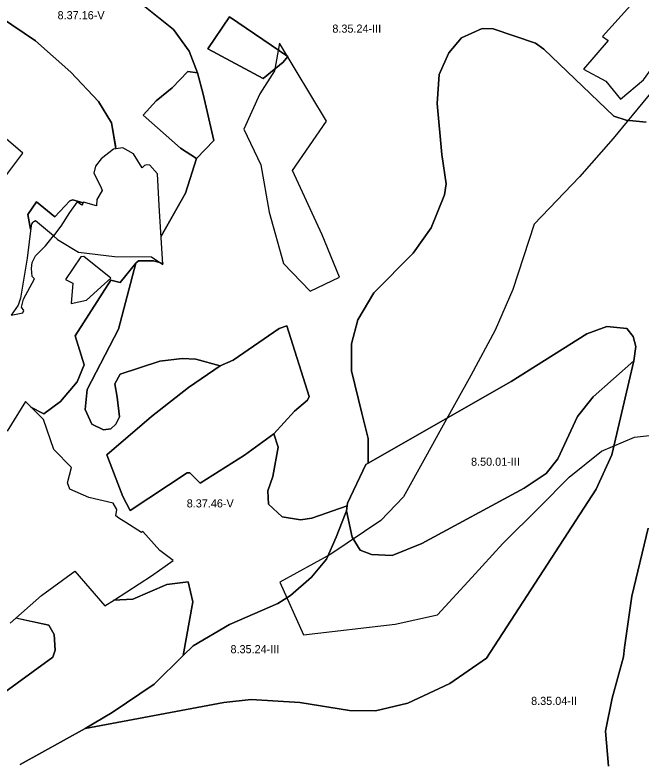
# Model space of a CAD drawing. Extents: x -547623 to -533936, y -1096714 to -1086523.
# Drawn here: x -542357 to -541585, y -1092131 to -1091207 of the extents above; entities that cross this region are included whole.
import ezdxf

# ---------------------------------------------------------------- set-up
doc = ezdxf.new("R2010")
doc.units = 0
for name, color, linetype in [('Vrstva 27', 7, 'Continuous'), ('Vrstva 28', 7, 'Continuous'), ('Vrstva 29', 7, 'Continuous')]:
    doc.layers.add(name, color=color, linetype=linetype)

msp = doc.modelspace()

# ---------------------------------------------------------------- linework, layer by layer
at = {"layer": 'Vrstva 28'}
for p, q in [((-542254, -1091151), (-542161.5, -1091225)), ((-542375, -1091210), (-542332, -1091239)), ((-542332, -1091239), (-542375, -1091210)), ((-542092.5, -1091209.5), (-542119.5, -1091249)), ((-542119.5, -1091249), (-542092.5, -1091209.5)), ((-542020.5, -1091258.5), (-542092.5, -1091209.5)), ((-542092.5, -1091209.5), (-542020.5, -1091258.5)), ((-542161.5, -1091225), (-542142.5, -1091252)), ((-541806.5, -1091235.5), (-541781, -1091224)), ((-541781, -1091224), (-541767.5, -1091224.5)), ((-541767.5, -1091224.5), (-541715, -1091242)), ((-542332, -1091239), (-542288.5, -1091278)), ((-542288.5, -1091278), (-542332, -1091239)), ((-541822, -1091254), (-541806.5, -1091235.5)), ((-541715, -1091242), (-541705, -1091249.5)), ((-542142.5, -1091252), (-542132, -1091278.5)), ((-542119.5, -1091249), (-542051, -1091285.5)), ((-542051, -1091285.5), (-542119.5, -1091249)), ((-541705, -1091249.5), (-541618.5, -1091332)), ((-542026.5, -1091265.5), (-542020.5, -1091258.5)), ((-542020.5, -1091258.5), (-542026.5, -1091265.5)), ((-541834, -1091280.5), (-541822, -1091254)), ((-542051, -1091285.5), (-542026.5, -1091265.5)), ((-542026.5, -1091265.5), (-542051, -1091285.5)), ((-542288.5, -1091278), (-542254, -1091314)), ((-542254, -1091314), (-542288.5, -1091278)), ((-542144, -1091277), (-542163.5, -1091297)), ((-542163.5, -1091297), (-542144, -1091277)), ((-542132, -1091278.5), (-542144, -1091277)), ((-542144, -1091277), (-542132, -1091278.5)), ((-542132, -1091278.5), (-542125, -1091305)), ((-541836.5, -1091316.5), (-541834, -1091280.5)), ((-542163.5, -1091297), (-542183, -1091313)), ((-542183, -1091313), (-542163.5, -1091297)), ((-542125, -1091305), (-542112, -1091362)), ((-542254, -1091314), (-542238, -1091340.5)), ((-542238, -1091340.5), (-542254, -1091314)), ((-542183, -1091313), (-542199, -1091331)), ((-542199, -1091331), (-542183, -1091313)), ((-541830.5, -1091379.5), (-541836.5, -1091316.5)), ((-542199, -1091331), (-542153, -1091371.5)), ((-542153, -1091371.5), (-542199, -1091331)), ((-541618.5, -1091332), (-541603.5, -1091337)), ((-542232.77, -1091372.41), (-542238, -1091340.5)), ((-542238, -1091340.5), (-542233.02, -1091370.85)), ((-541603.5, -1091337), (-541578.5, -1091339.5)), ((-542112, -1091362), (-542133.5, -1091384.5)), ((-542153, -1091371.5), (-542133.5, -1091384.5)), ((-542133.5, -1091384.5), (-542153, -1091371.5)), ((-541825.5, -1091415.5), (-541830.5, -1091379.5)), ((-542133.5, -1091384.5), (-542147, -1091427)), ((-541827.5, -1091429), (-541825.5, -1091415.5)), ((-542147, -1091427), (-542177.27, -1091480.98)), ((-542289.5, -1091436.5), (-542308, -1091456.5)), ((-542286, -1091435.5), (-542289.5, -1091436.5)), ((-542273.14, -1091439.05), (-542286, -1091435.5)), ((-541844, -1091470), (-541827.5, -1091429)), ((-542330.5, -1091438), (-542341.5, -1091453.5)), ((-542308, -1091456.5), (-542330.5, -1091438)), ((-542341.5, -1091453.5), (-542338, -1091471.5)), ((-541866, -1091501), (-541844, -1091470)), ((-541914.5, -1091550), (-541866, -1091501)), ((-542208, -1091513.5), (-542229.5, -1091595)), ((-542227.5, -1091537.5), (-542208, -1091513.5)), ((-542283, -1091603), (-542239, -1091534.5)), ((-542239, -1091534.5), (-542227.5, -1091537.5)), ((-541934.5, -1091583.5), (-541914.5, -1091550)), ((-541942, -1091613), (-541934.5, -1091583.5)), ((-542229.5, -1091595), (-542268, -1091669.5)), ((-542088, -1091633), (-542031.5, -1091594)), ((-542031.5, -1091594), (-542022, -1091591)), ((-542022, -1091591), (-541994.5, -1091678)), ((-541627, -1091591.5), (-541652, -1091600.5)), ((-541652, -1091600.5), (-541627, -1091591.5)), ((-541602.5, -1091594), (-541627, -1091591.5)), ((-541627, -1091591.5), (-541602.5, -1091594)), ((-541594.5, -1091604), (-541602.5, -1091594)), ((-541602.5, -1091594), (-541594.5, -1091604)), ((-542272, -1091639), (-542283, -1091603)), ((-541652, -1091600.5), (-541745, -1091659.5)), ((-541745, -1091659.5), (-541652, -1091600.5)), ((-541591.5, -1091616.5), (-541594.5, -1091604)), ((-541594.5, -1091604), (-541591.5, -1091616.5)), ((-541942, -1091646.5), (-541942, -1091613)), ((-541594, -1091634), (-541591.5, -1091616.5)), ((-541591.5, -1091616.5), (-541594, -1091634)), ((-542178.5, -1091634.5), (-542151, -1091631)), ((-542151, -1091631), (-542134, -1091632)), ((-542134, -1091632), (-542104, -1091640)), ((-542280.5, -1091660), (-542272, -1091639)), ((-542227.5, -1091650.5), (-542178.5, -1091634.5)), ((-542104, -1091640), (-542143, -1091667)), ((-542143, -1091667), (-542104, -1091640)), ((-542104, -1091640), (-542088, -1091633)), ((-541644, -1091678.5), (-541594, -1091634)), ((-541594, -1091634), (-541644, -1091678.5)), ((-541621, -1091750), (-541594, -1091634)), ((-541594, -1091634), (-541621, -1091750)), ((-542234, -1091662.5), (-542227.5, -1091650.5)), ((-541929.5, -1091698.5), (-541942, -1091646.5)), ((-541745, -1091659.5), (-541921.5, -1091760.29)), ((-541921.5, -1091760.29), (-541745, -1091659.5)), ((-542301, -1091684), (-542280.5, -1091660)), ((-542231, -1091679), (-542234, -1091662.5)), ((-542143, -1091667), (-542189, -1091702.5)), ((-542189, -1091702.5), (-542143, -1091667)), ((-542268, -1091669.5), (-542270.5, -1091694)), ((-541994.5, -1091678), (-541996.5, -1091682.5)), ((-542321.5, -1091699.5), (-542301, -1091684)), ((-542228.5, -1091703), (-542231, -1091679)), ((-541996.5, -1091682.5), (-542012.5, -1091696)), ((-541663.5, -1091702.5), (-541644, -1091678.5)), ((-541644, -1091678.5), (-541663.5, -1091702.5)), ((-542337.48, -1091691.09), (-542321.5, -1091699.5)), ((-542270.5, -1091694), (-542262.5, -1091712)), ((-542012.5, -1091696), (-542038, -1091724)), ((-542189, -1091702.5), (-542244, -1091750)), ((-542244, -1091750), (-542189, -1091702.5)), ((-542233, -1091712), (-542228.5, -1091703)), ((-541921.5, -1091730), (-541929.5, -1091698.5)), ((-541687.5, -1091755), (-541663.5, -1091702.5)), ((-541663.5, -1091702.5), (-541687.5, -1091755)), ((-542262.5, -1091712), (-542248, -1091719)), ((-542239, -1091718), (-542233, -1091712)), ((-542248, -1091719), (-542239, -1091718)), ((-542074, -1091750.5), (-542038, -1091724)), ((-542038, -1091724), (-542074, -1091750.5)), ((-542038, -1091724), (-542032.5, -1091740.5)), ((-541921.5, -1091760.29), (-541921.5, -1091730)), ((-542032.5, -1091740.5), (-542039, -1091776.5)), ((-542244, -1091750), (-542224, -1091801.5)), ((-542224, -1091801.5), (-542244, -1091750)), ((-542129, -1091785), (-542074, -1091750.5)), ((-542074, -1091750.5), (-542129, -1091785)), ((-541640.5, -1091792.5), (-541621, -1091750)), ((-541621, -1091750), (-541640.5, -1091792.5)), ((-541924.5, -1091762), (-541921.5, -1091760.29)), ((-541702, -1091773), (-541687.5, -1091755)), ((-541687.5, -1091755), (-541702, -1091773)), ((-541947, -1091809.5), (-541924.5, -1091762)), ((-542215, -1091818.5), (-542145, -1091772)), ((-542145, -1091772), (-542215, -1091818.5)), ((-542145, -1091772), (-542141.5, -1091772)), ((-542141.5, -1091772), (-542145, -1091772)), ((-542141.5, -1091772), (-542129, -1091785)), ((-542129, -1091785), (-542141.5, -1091772)), ((-542039, -1091776.5), (-542045.5, -1091794.5)), ((-541729, -1091791), (-541702, -1091773)), ((-541702, -1091773), (-541729, -1091791)), ((-542045.5, -1091794.5), (-542044.5, -1091811)), ((-541855.5, -1091859.5), (-541729, -1091791)), ((-541729, -1091791), (-541855.5, -1091859.5)), ((-541775.5, -1092001), (-541640.5, -1091792.5)), ((-541640.5, -1091792.5), (-541775.5, -1092001)), ((-542224, -1091801.5), (-542215, -1091818.5)), ((-542215, -1091818.5), (-542224, -1091801.5)), ((-542044.5, -1091811), (-542027.5, -1091826.5)), ((-541991, -1091828), (-541947.5, -1091813)), ((-541947.5, -1091813), (-541948.39, -1091819.23)), ((-541948.39, -1091819.23), (-541947.5, -1091813)), ((-541947.5, -1091813), (-541947, -1091809.5)), ((-541961, -1091851.5), (-541949.92, -1091823.14)), ((-541949.92, -1091823.14), (-541961, -1091851.5)), ((-541949.92, -1091823.14), (-541948.39, -1091819.23)), ((-541948.39, -1091819.23), (-541949.92, -1091823.14)), ((-541948.39, -1091819.23), (-541941.5, -1091851.5)), ((-541941.5, -1091851.5), (-541948.39, -1091819.23)), ((-542027.5, -1091826.5), (-542005, -1091830)), ((-542005, -1091830), (-541991, -1091828)), ((-541576, -1091840.5), (-541596.5, -1091924.5)), ((-541973, -1091878.5), (-541961, -1091851.5)), ((-541961, -1091851.5), (-541973, -1091878.5)), ((-541941.5, -1091851.5), (-541931.5, -1091867.5)), ((-541931.5, -1091867.5), (-541941.5, -1091851.5)), ((-541892, -1091874), (-541855.5, -1091859.5)), ((-541855.5, -1091859.5), (-541892, -1091874)), ((-541931.5, -1091867.5), (-541917.5, -1091873)), ((-541917.5, -1091873), (-541931.5, -1091867.5)), ((-541991.5, -1091901), (-541973, -1091878.5)), ((-541973, -1091878.5), (-541991.5, -1091901)), ((-541917.5, -1091873), (-541892, -1091874)), ((-541892, -1091874), (-541917.5, -1091873)), ((-542170, -1091910), (-542143.5, -1091906.5)), ((-542143.5, -1091906.5), (-542170, -1091910)), ((-542143.5, -1091906.5), (-542138, -1091931.5)), ((-542138, -1091931.5), (-542143.5, -1091906.5)), ((-542017.5, -1091923.5), (-541991.5, -1091901)), ((-541991.5, -1091901), (-542017.5, -1091923.5)), ((-542212, -1091928), (-542170, -1091910)), ((-542170, -1091910), (-542212, -1091928)), ((-542033, -1091933.5), (-542017.5, -1091923.5)), ((-542017.5, -1091923.5), (-542033, -1091933.5)), ((-541596.5, -1091924.5), (-541605.5, -1091987.5)), ((-542212, -1091928), (-542235.83, -1091929.32)), ((-542235.83, -1091929.32), (-542212, -1091928)), ((-542138, -1091931.5), (-542149.82, -1091997.69)), ((-542149.82, -1091997.69), (-542138, -1091931.5)), ((-542092.5, -1091959.5), (-542033, -1091933.5)), ((-542033, -1091933.5), (-542092.5, -1091959.5)), ((-542315.5, -1091960), (-542356.23, -1091951.31)), ((-542353, -1091952), (-542315.5, -1091960)), ((-542309, -1091971.5), (-542315.5, -1091960)), ((-542315.5, -1091960), (-542309, -1091971.5)), ((-542137.5, -1091985.5), (-542092.5, -1091959.5)), ((-542092.5, -1091959.5), (-542137.5, -1091985.5)), ((-542307.5, -1091991), (-542309, -1091971.5)), ((-542309, -1091971.5), (-542307.5, -1091991)), ((-542310.5, -1091999.5), (-542307.5, -1091991)), ((-542307.5, -1091991), (-542310.5, -1091999.5)), ((-542149.82, -1091997.69), (-542137.5, -1091985.5)), ((-542137.5, -1091985.5), (-542149.82, -1091997.69)), ((-541605.5, -1091987.5), (-541606.5, -1091999)), ((-542398, -1092063), (-542310.5, -1091999.5)), ((-542310.5, -1091999.5), (-542398, -1092063)), ((-542185.5, -1092033), (-542149.82, -1091997.69)), ((-542149.82, -1091997.69), (-542185.5, -1092033)), ((-541821, -1092032), (-541775.5, -1092001)), ((-541775.5, -1092001), (-541821, -1092032)), ((-541606.5, -1091999), (-541620.5, -1092050)), ((-542237.5, -1092068), (-542185.5, -1092033)), ((-542185.5, -1092033), (-542237.5, -1092068)), ((-541872.5, -1092056.5), (-541821, -1092032)), ((-541821, -1092032), (-541872.5, -1092056.5)), ((-542270.5, -1092087.5), (-542099.5, -1092055.5)), ((-542099.5, -1092055.5), (-542270.5, -1092087.5)), ((-542099.5, -1092055.5), (-542066, -1092052)), ((-542066, -1092052), (-542099.5, -1092055.5)), ((-542066, -1092052), (-542006, -1092055.5)), ((-542006, -1092055.5), (-542066, -1092052)), ((-542006, -1092055.5), (-541944.5, -1092065.5)), ((-541944.5, -1092065.5), (-542006, -1092055.5)), ((-541912.5, -1092066), (-541872.5, -1092056.5)), ((-541872.5, -1092056.5), (-541912.5, -1092066)), ((-541620.5, -1092050), (-541629, -1092091)), ((-541944.5, -1092065.5), (-541912.5, -1092066)), ((-541912.5, -1092066), (-541944.5, -1092065.5)), ((-542270.5, -1092087.5), (-542237.5, -1092068)), ((-542237.5, -1092068), (-542270.5, -1092087.5)), ((-542351, -1092132), (-542270.5, -1092087.5)), ((-542270.5, -1092087.5), (-542351, -1092132)), ((-541629, -1092091), (-541625, -1092134))]:
    msp.add_line(p, q, dxfattribs=at)
for points in [[(-542176.82, -1091480.17), (-542147, -1091427), (-542133.5, -1091384.5), (-542112, -1091362), (-542125, -1091305), (-542132, -1091278.5), (-542142.5, -1091252), (-542161.5, -1091225), (-542254, -1091151), (-542266, -1091141), (-542245.5, -1091142), (-542209.5, -1091137.5), (-542177, -1091112), (-542160.5, -1091087), (-542142, -1091044.5), (-542135.5, -1091006), (-542138.9, -1090982.21)], [(-542470.5, -1091150), (-542375, -1091210), (-542332, -1091239), (-542288.5, -1091278), (-542254, -1091314), (-542238, -1091340.5), (-542233.12, -1091370.25)], [(-542161.5, -1091225), (-542254, -1091151)], [(-541598.01, -1091195.68), (-541632.32, -1091233.95), (-541625.35, -1091238.85), (-541656.01, -1091274.32), (-541628.2, -1091289.12), (-541610.51, -1091311.34), (-541582.05, -1091287.09), (-541569.93, -1091270.69), (-541553.43, -1091249.53), (-541539.32, -1091231.42), (-541506.84, -1091190.12)], [(-542119.5, -1091249), (-542051, -1091285.5), (-542026.5, -1091265.5), (-542020.5, -1091258.5), (-542092.5, -1091209.5), (-542119.5, -1091249)], [(-541578.5, -1091339.5), (-541603.5, -1091337), (-541618.5, -1091332), (-541705, -1091249.5), (-541715, -1091242), (-541767.5, -1091224.5), (-541781, -1091224), (-541806.5, -1091235.5), (-541822, -1091254), (-541834, -1091280.5), (-541836.5, -1091316.5), (-541830.5, -1091379.5), (-541825.5, -1091415.5), (-541827.5, -1091429), (-541844, -1091470), (-541866, -1091501), (-541914.5, -1091550), (-541934.5, -1091583.5), (-541942, -1091613), (-541942, -1091646.5), (-541929.5, -1091698.5), (-541921.5, -1091730), (-541921.5, -1091760.29), (-541924.5, -1091762), (-541947, -1091809.5), (-541947.5, -1091813), (-541991, -1091828), (-542005, -1091830), (-542027.5, -1091826.5), (-542044.5, -1091811), (-542045.5, -1091794.5), (-542039, -1091776.5), (-542032.5, -1091740.5), (-542038, -1091724), (-542012.5, -1091696), (-541996.5, -1091682.5), (-541994.5, -1091678), (-542022, -1091591), (-542031.5, -1091594), (-542088, -1091633), (-542104, -1091640), (-542134, -1091632), (-542151, -1091631), (-542178.5, -1091634.5), (-542227.5, -1091650.5), (-542234, -1091662.5), (-542231, -1091679), (-542228.5, -1091703), (-542233, -1091712), (-542239, -1091718), (-542248, -1091719), (-542262.5, -1091712), (-542270.5, -1091694), (-542268, -1091669.5), (-542229.5, -1091595), (-542208, -1091513.5), (-542205, -1091510.5), (-542186.5, -1091510.5), (-542174.5, -1091514), (-542174.58, -1091512.88)], [(-542176.82, -1091480.17), (-542147, -1091427), (-542133.5, -1091384.5), (-542153, -1091371.5), (-542199, -1091331), (-542183, -1091313), (-542163.5, -1091297), (-542144, -1091277), (-542132, -1091278.5), (-542142.5, -1091252), (-542161.5, -1091225)], [(-541578.5, -1091339.5), (-541603.5, -1091337), (-541618.5, -1091332), (-541705, -1091249.5), (-541715, -1091242), (-541767.5, -1091224.5), (-541781, -1091224), (-541806.5, -1091235.5), (-541822, -1091254), (-541834, -1091280.5), (-541836.5, -1091316.5), (-541830.5, -1091379.5), (-541825.5, -1091415.5)], [(-542112, -1091362), (-542125, -1091305), (-542132, -1091278.5), (-542144, -1091277), (-542163.5, -1091297), (-542183, -1091313), (-542199, -1091331), (-542153, -1091371.5), (-542133.5, -1091384.5), (-542112, -1091362)], [(-542421.04, -1091385.69), (-542380.14, -1091420.72), (-542347.44, -1091377.7), (-542388.57, -1091342.81), (-542421.04, -1091385.69)], [(-542289.89, -1091450.79), (-542300.86, -1091467.71), (-542309.83, -1091479.9), (-542304.79, -1091484.13), (-542278.99, -1091500.07), (-542234.34, -1091505.44), (-542188.73, -1091505.77), (-542174.73, -1091515.26), (-542179.18, -1091442.23), (-542181.56, -1091403.18), (-542190.87, -1091392.48), (-542194.57, -1091392.03), (-542197.29, -1091393.03), (-542200.48, -1091395.66), (-542211.22, -1091378.72), (-542224.39, -1091371.18), (-542235.55, -1091372.73), (-542250.83, -1091384.87), (-542257.92, -1091393.91), (-542259.95, -1091402.49), (-542251.31, -1091419.41), (-542249.82, -1091423.77), (-542256.07, -1091434.94), (-542256.86, -1091442.66), (-542272.56, -1091438.19), (-542273.56, -1091439.78), (-542274.96, -1091442), (-542280.65, -1091437.92), (-542289.89, -1091450.79)], [(-541825.5, -1091415.5), (-541827.5, -1091429), (-541844, -1091470), (-541866, -1091501), (-541914.5, -1091550), (-541934.5, -1091583.5), (-541942, -1091613), (-541942, -1091646.5), (-541929.5, -1091698.5), (-541921.5, -1091730), (-541921.5, -1091760.29), (-541745, -1091659.5), (-541652, -1091600.5), (-541627, -1091591.5), (-541602.5, -1091594), (-541594.5, -1091604), (-541591.5, -1091616.5), (-541594, -1091634), (-541621, -1091750), (-541640.5, -1091792.5), (-541775.5, -1092001), (-541821, -1092032), (-541872.5, -1092056.5), (-541912.5, -1092066), (-541944.5, -1092065.5), (-542006, -1092055.5), (-542066, -1092052), (-542099.5, -1092055.5), (-542270.5, -1092087.5), (-542351, -1092132)], [(-542338, -1091471.5), (-542341.5, -1091453.5), (-542330.5, -1091438), (-542308, -1091456.5), (-542289.5, -1091436.5), (-542286, -1091435.5), (-542273.41, -1091438.97)], [(-542309.83, -1091479.9), (-542332.08, -1091461.23), (-542334.15, -1091462.33), (-542335.5, -1091463.49), (-542336.64, -1091464.7), (-542337.45, -1091467), (-542342.34, -1091507.21), (-542348.63, -1091546.81), (-542350.46, -1091556.49), (-542353.46, -1091565.22), (-542361.8, -1091577.48), (-542347.64, -1091574.68), (-542346.13, -1091571.83), (-542349.02, -1091567.94), (-542346.76, -1091557.93), (-542333.1, -1091532.96), (-542336.05, -1091529.74), (-542336.97, -1091519.95), (-542335.99, -1091512.51), (-542331.93, -1091504.44), (-542319.71, -1091491.97), (-542309.83, -1091479.9)], [(-542174.85, -1091513.9), (-542186.5, -1091510.5), (-542205, -1091510.5), (-542208, -1091513.5), (-542227.5, -1091537.5), (-542239, -1091534.5), (-542283, -1091603), (-542272, -1091639), (-542280.5, -1091660), (-542301, -1091684), (-542321.5, -1091699.5), (-542337.48, -1091691.09)], [(-542246.87, -1091539.17), (-542243.02, -1091535.7), (-542239.12, -1091532.18), (-542272.35, -1091505.42), (-542276.15, -1091505.86), (-542294.98, -1091533.61), (-542285.77, -1091537.99), (-542288.06, -1091563.16), (-542269.02, -1091559.13), (-542246.87, -1091539.17)], [(-542129, -1091785), (-542074, -1091750.5), (-542038, -1091724), (-542012.5, -1091696), (-541996.5, -1091682.5), (-541994.5, -1091678), (-542022, -1091591), (-542031.5, -1091594), (-542088, -1091633), (-542104, -1091640), (-542143, -1091667), (-542189, -1091702.5), (-542244, -1091750), (-542224, -1091801.5), (-542215, -1091818.5), (-542145, -1091772), (-542141.5, -1091772), (-542129, -1091785)], [(-541745, -1091659.5), (-541921.5, -1091760.29), (-541924.5, -1091762), (-541947, -1091809.5), (-541947.5, -1091813), (-541948.39, -1091819.23), (-541941.5, -1091851.5), (-541931.5, -1091867.5), (-541917.5, -1091873), (-541892, -1091874), (-541855.5, -1091859.5), (-541729, -1091791), (-541702, -1091773), (-541687.5, -1091755), (-541663.5, -1091702.5), (-541644, -1091678.5), (-541594, -1091634), (-541591.5, -1091616.5), (-541594.5, -1091604), (-541602.5, -1091594), (-541627, -1091591.5), (-541652, -1091600.5), (-541745, -1091659.5)], [(-541729, -1091791), (-541855.5, -1091859.5), (-541892, -1091874), (-541917.5, -1091873), (-541931.5, -1091867.5), (-541941.5, -1091851.5), (-541948.39, -1091819.23), (-541949.92, -1091823.14), (-541961, -1091851.5), (-541973, -1091878.5), (-541991.5, -1091901), (-542017.5, -1091923.5), (-542033, -1091933.5), (-542092.5, -1091959.5), (-542137.5, -1091985.5), (-542149.82, -1091997.69), (-542185.5, -1092033), (-542237.5, -1092068), (-542270.5, -1092087.5), (-542099.5, -1092055.5), (-542066, -1092052), (-542006, -1092055.5), (-541944.5, -1092065.5), (-541912.5, -1092066), (-541872.5, -1092056.5), (-541821, -1092032), (-541775.5, -1092001), (-541640.5, -1091792.5), (-541621, -1091750), (-541594, -1091634), (-541644, -1091678.5), (-541663.5, -1091702.5), (-541687.5, -1091755), (-541702, -1091773), (-541729, -1091791)], [(-542363.06, -1091957.81), (-542324.59, -1091923.69), (-542283.58, -1091893.68), (-542246.38, -1091936.31), (-542234.64, -1091928.78), (-542188.88, -1091899.43), (-542162.04, -1091880.51), (-542178.75, -1091868.1), (-542199.38, -1091844.47), (-542201.13, -1091845.92), (-542220.59, -1091833.44), (-542229.17, -1091827.94), (-542232.89, -1091825.15), (-542231.48, -1091817.41), (-542235.95, -1091809.64), (-542266.27, -1091802.79), (-542289.4, -1091792.18), (-542292.27, -1091784.66), (-542287.37, -1091765.51), (-542309.15, -1091743.41), (-542322.04, -1091706.3), (-542344.3, -1091684.07), (-542366.69, -1091720.95)], [(-541625, -1092134), (-541629, -1092091), (-541620.5, -1092050), (-541606.5, -1091999), (-541605.5, -1091987.5), (-541596.5, -1091924.5), (-541576, -1091840.5)], [(-541625, -1092134), (-541629, -1092091), (-541620.5, -1092050), (-541606.5, -1091999), (-541605.5, -1091987.5), (-541596.5, -1091924.5), (-541576, -1091840.5)]]:
    msp.add_lwpolyline(points, dxfattribs=at)
at = {"layer": 'Vrstva 29'}
for points in [[(-541956.79, -1091530.62), (-541978.21, -1091478.35), (-542014.89, -1091399.32), (-541973.16, -1091338.31), (-542030.97, -1091241.87), (-542037.01, -1091276.04), (-542055.22, -1091304.53), (-542075.09, -1091348.2), (-542053.79, -1091392.27), (-542043.52, -1091450.49), (-542025.86, -1091513.88), (-541993.01, -1091548.19), (-541956.79, -1091530.62)], [(-541559.84, -1091287.31), (-541619.19, -1091359.72), (-541660.7, -1091406.92), (-541716.99, -1091465.33), (-541742.95, -1091545.98), (-541765.05, -1091596.07), (-541794.74, -1091652.25), (-541831.26, -1091717.16), (-541851.01, -1091752.65), (-541877.87, -1091801.71), (-541905.91, -1091831.18), (-541967.74, -1091872.33), (-542030.68, -1091907.22), (-542001.14, -1091971.9), (-541888.4, -1091959.09), (-541835.93, -1091947.39), (-541793.52, -1091901.3), (-541755.41, -1091859.36), (-541710.34, -1091814.59), (-541673.51, -1091777.37), (-541633.92, -1091745.32), (-541592.89, -1091728.28), (-541545.47, -1091722.95)]]:
    msp.add_lwpolyline(points, dxfattribs=at)

# ---------------------------------------------------------------- texts
at = {"layer": 'Vrstva 27'}
for s, p in [('8.37.16-V', (-542304.7, -1091212.52)), ('8.35.24-III', (-541965.74, -1091229.09)), ('8.50.01-III', (-541794.68, -1091763.45)), ('8.37.46-V', (-542145.36, -1091814.88)), ('8.35.24-III', (-542091.37, -1091994.76)), ('8.35.04-II', (-541720.55, -1092058.55))]:
    msp.add_text(s, height=10, dxfattribs=at).set_placement(p)

doc.saveas('drawing.dxf')
